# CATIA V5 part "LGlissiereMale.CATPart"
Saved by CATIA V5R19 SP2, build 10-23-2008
Part number: GlissièreMale
Publications: "Centre", "Axe", "Plan", "Facteur d'échelle"
Bounding box of the stored display mesh (mm): x -12.498 to 12.498, y -12.498 to 12.498, z -37.5 to 37.5
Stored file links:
  E:\Mes documents\03_Ressources pédagogiques\01_Catia\Buggy Dassault\SchemaCinematiqueFinal\LGlissiereMale.CATPart
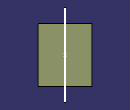
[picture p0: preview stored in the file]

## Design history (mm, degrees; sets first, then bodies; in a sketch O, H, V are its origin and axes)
Parameters
  `Facteur d'échelle` = 5
Body1 "GlissièreMale" (main body)
  Point1 "Centre": (0, 0, 0)
  Line1 "Axe": type PtPt, FirstPoint {point type Coord, X 0, Y 0, Z -37.5 {= -7.5mm*`Facteur d'échelle`}}, SecondPoint {point type Coord, X 0, Y 0, Z 37.5 {= 7.5mm*`Facteur d'échelle`}}, Support zx-plane
  Sketch1 on xy-plane, origin (0, 0, 0), H (1, 0, 0), V (0, 1, 0)
    line L1 (-12.4981, 12.4981) -> (12.4981, -12.4981)
    point P1 (-12.4981, 12.4981)
    point P2 (12.4981, -12.4981)
    reference intersected line E1 through (0, 0) direction (-1, 0) from zx-plane
    reference intersected line E2 through (0, 0) direction (0, 1) from yz-plane
    distance P2 P1 = 35.35 {= 1.414*5mm*`Facteur d'échelle`}
    midpoint: O L1
    symmetry: E1 E2 L1
  Sketch2 on xy-plane, origin (0, 0, 0), H (1, 0, 0), V (0, 1, 0)
    line L1 (12.4981, 12.4981) -> (-12.4981, -12.4981)
    point P1 (12.4981, 12.4981)
    point P2 (-12.4981, -12.4981)
    reference intersected line E1 through (0, 0) direction (-1, 0) from zx-plane
    reference intersected line E2 through (0, 0) direction (0, 1) from yz-plane
    distance P2 P1 = 35.35 {= 1.414*5mm*`Facteur d'échelle`}
    midpoint: O L1
    symmetry: E1 E2 L1
  Extrude1 "Extrusion.1": Element1 Sketch1, Lim1 25 {= 5mm*`Facteur d'échelle`}, Lim2 25 {= 5mm*`Facteur d'échelle`}, Direction xy-plane
  Extrude2 "Extrusion.2": Element1 Sketch2, Lim1 25 {= 5mm*`Facteur d'échelle`}, Lim2 25 {= 5mm*`Facteur d'échelle`}, Direction xy-plane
